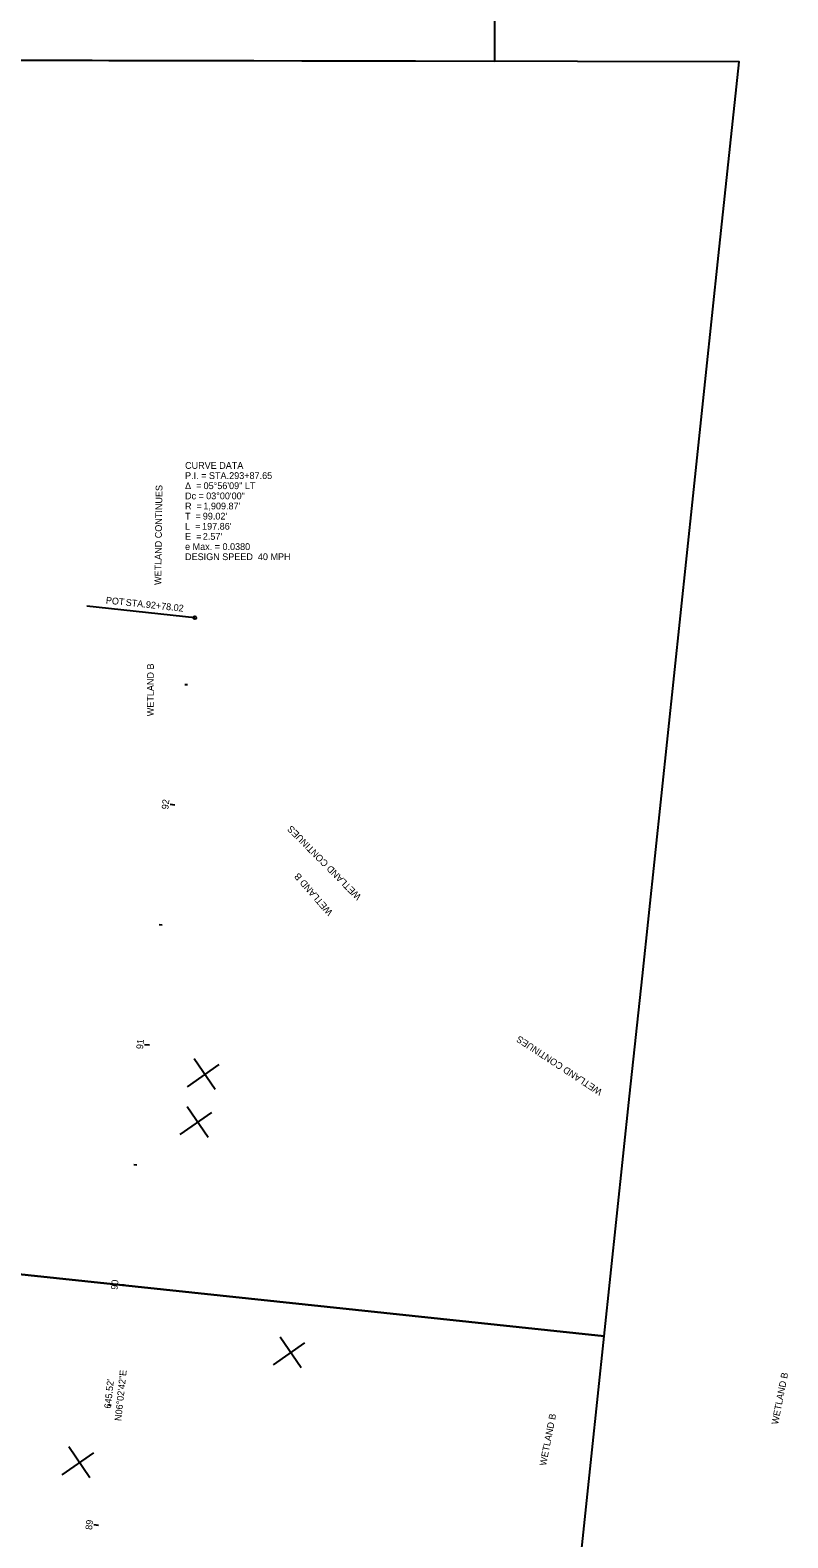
# Model space of a CAD drawing. Extents: x 172043 to 172958, y 249504 to 260295.
# Drawn here: x 172554 to 172867, y 255788 to 256412 of the extents above; entities that cross this region are included whole.
import ezdxf

# ---------------------------------------------------------------- set-up
doc = ezdxf.new("R2010")
doc.units = 0
for name, color, linetype in [('BD_X_Building', 7, 'Continuous'), ('DR_X_Storm_Sewer', 7, 'Continuous'), ('LT_X_Poles', 7, 'Continuous'), ('RS_Raster1', 7, 'Continuous'), ('RW_X_CL_100_Bearings', 7, 'Continuous'), ('RW_X_CL_100_Cardinal_Points', 7, 'Continuous'), ('RW_X_CL_100_Curve_Data', 7, 'Continuous'), ('RW_X_CL_100_Stations', 7, 'Continuous')]:
    doc.layers.add(name, color=color, linetype=linetype)

msp = doc.modelspace()

# ---------------------------------------------------------------- linework, layer by layer
at = {"layer": 'BD_X_Building'}
for p, q in [((172630.16, 255973.29), (172621.5, 255986.04)), ((172618.65, 255974.51), (172631.75, 255983.64)), ((172627.2, 255953.46), (172618.55, 255966.21)), ((172615.7, 255954.68), (172628.8, 255963.82)), ((172654.25, 255859.31), (172667.35, 255868.44)), ((172665.76, 255858.08), (172657.1, 255870.83)), ((172566.74, 255813.79), (172579.84, 255822.92)), ((172578.25, 255812.56), (172569.59, 255825.31))]:
    msp.add_line(p, q, dxfattribs=at)
at = {"layer": 'DR_X_Storm_Sewer'}
for points in [[(172345.99, 256399.91), (172745.99, 256399.15), (172746.09, 256449.15), (172746.18, 256499.15), (172746.28, 256549.15), (172746.37, 256599.15), (172746.66, 256647.48), (172747.36, 256695.73), (172748.49, 256743.97), (172750.04, 256792.2), (172752.01, 256840.45), (172754.37, 256888.9), (172354.92, 256909.87), (172352.41, 256858.44), (172350.3, 256806.77), (172348.64, 256755.05), (172347.43, 256703.32), (172346.68, 256651.58), (172346.37, 256599.91), (172346.28, 256549.91), (172346.18, 256499.91), (172346.09, 256449.91)], [(172393.52, 255913.31), (172791.29, 255871.19), (172796.56, 255920.91), (172801.83, 255970.63), (172807.09, 256020.35), (172812.36, 256070.07), (172817.62, 256119.8), (172822.89, 256169.52), (172828.15, 256219.24), (172833.42, 256268.96), (172838.68, 256318.68), (172847.18, 256398.96), (172445.03, 256399.72), (172440.91, 256360.81), (172435.64, 256311.09), (172430.38, 256261.36), (172425.11, 256211.64), (172419.85, 256161.92), (172414.58, 256112.2), (172409.32, 256062.48), (172404.05, 256012.75), (172398.78, 255963.03)], [(172320.75, 255469.43), (172697.36, 255334.65), (172714.21, 255381.73), (172731.06, 255428.8), (172754.44, 255523.13), (172759.7, 255572.85), (172764.97, 255622.58), (172770.23, 255672.3), (172775.5, 255722.02), (172780.76, 255771.74), (172786.03, 255821.46), (172791.29, 255871.19), (172393.52, 255913.31), (172388.25, 255863.59), (172382.99, 255813.87), (172377.72, 255764.14), (172372.46, 255714.42), (172367.19, 255664.7), (172361.93, 255614.98), (172356.66, 255565.26), (172354.45, 255563.58), (172337.6, 255516.51)]]:
    msp.add_lwpolyline(points, close=True, dxfattribs=at)
at = {"layer": 'RW_X_CL_100_Bearings'}
msp.add_line((172621.69, 256168.73), (172576.94, 256173.47), dxfattribs=at)
msp.add_circle((172621.69, 256168.73), 0.6, dxfattribs=at)
at = {"layer": 'RW_X_CL_100_Stations'}
for p, q in [((172618.73, 256140.86), (172617.54, 256140.98)), ((172613.47, 256091.14), (172611.48, 256091.35)), ((172608.2, 256041.41), (172607.01, 256041.54)), ((172602.94, 255991.69), (172600.95, 255991.9)), ((172597.67, 255941.97), (172596.48, 255942.1)), ((172592.41, 255892.25), (172590.42, 255892.46)), ((172587.14, 255842.53), (172585.95, 255842.65)), ((172581.88, 255792.8), (172579.89, 255793.02))]:
    msp.add_line(p, q, dxfattribs=at)

# ---------------------------------------------------------------- texts
at = {"layer": 'LT_X_Poles'}
for s, height, rotation, p in [('WETLAND CONTINUES', 2.8003, 89.2647, (172607.8, 256182.26)), ('WETLAND B', 2.8, 89.92451, (172604.73, 256127.92)), ('WETLAND CONTINUES', 2.8003, 134.73954, (172690.89, 256053.46)), ('WETLAND B', 2.8, 131.04533, (172679.06, 256046.84)), ('WETLAND CONTINUES', 2.8003, 146.70694, (172790.75, 255973.03)), ('WETLAND B', 2.8, 78.92183, (172863.29, 255834.44)), ('WETLAND B', 2.8, 78.92183, (172767.2, 255817.38))]:
    msp.add_text(s, height=height, rotation=rotation, dxfattribs=at).set_placement(p)
at = {"layer": 'RS_Raster1'}
msp.add_text('N06°02\'42"E', height=2.8, rotation=83.95499, dxfattribs=at).set_placement((172591.27, 255835.95))
at = {"layer": 'RW_X_CL_100_Bearings'}
for s, p in [('POT', (172584.77, 256174.62)), (' STA. ', (172591.94, 256173.86)), ('92+78.02', (172601.33, 256172.86))]:
    msp.add_text(s, height=2.8, rotation=353.95499, dxfattribs=at).set_placement(p)
at = {"layer": 'RW_X_CL_100_Cardinal_Points'}
for s, p in [('CURVE DATA', (172617.69, 256230.37)), ('P.I. = STA. ', (172617.69, 256226.17)), ('293+87.65', (172635.96, 256226.17)), ('Δ  = ', (172617.69, 256221.97)), ('05°56\'09" LT', (172625.37, 256221.97)), ('Dc = ', (172617.69, 256217.77)), ('R  = ', (172617.69, 256213.57)), ("1,909.87'", (172625.28, 256213.57)), ('03°00\'00"', (172626.43, 256217.77)), ('T  = ', (172617.69, 256209.37)), ("99.02'", (172625.03, 256209.37)), ('L  = ', (172617.69, 256205.17)), ('E  = ', (172617.69, 256200.97)), ("197.86'", (172624.74, 256205.17)), ("2.57'", (172625.03, 256200.97)), ('e Max. = 0.0380', (172617.69, 256196.77)), ('DESIGN SPEED  40 MPH', (172617.69, 256192.57))]:
    msp.add_text(s, height=2.8, dxfattribs=at).set_placement(p)
at = {"layer": 'RW_X_CL_100_Curve_Data'}
msp.add_text("645.52'", height=2.8, rotation=83.95499, dxfattribs=at).set_placement((172586.95, 255841.12))
at = {"layer": 'RW_X_CL_100_Stations'}
for s, p in [('92', (172610.75, 256089.25)), ('91', (172600.24, 255989.93)), ('90', (172589.69, 255890.29)), ('89', (172579.16, 255790.88))]:
    msp.add_text(s, height=2.8, rotation=83.95499, dxfattribs=at).set_placement(p)

doc.saveas('drawing.dxf')
